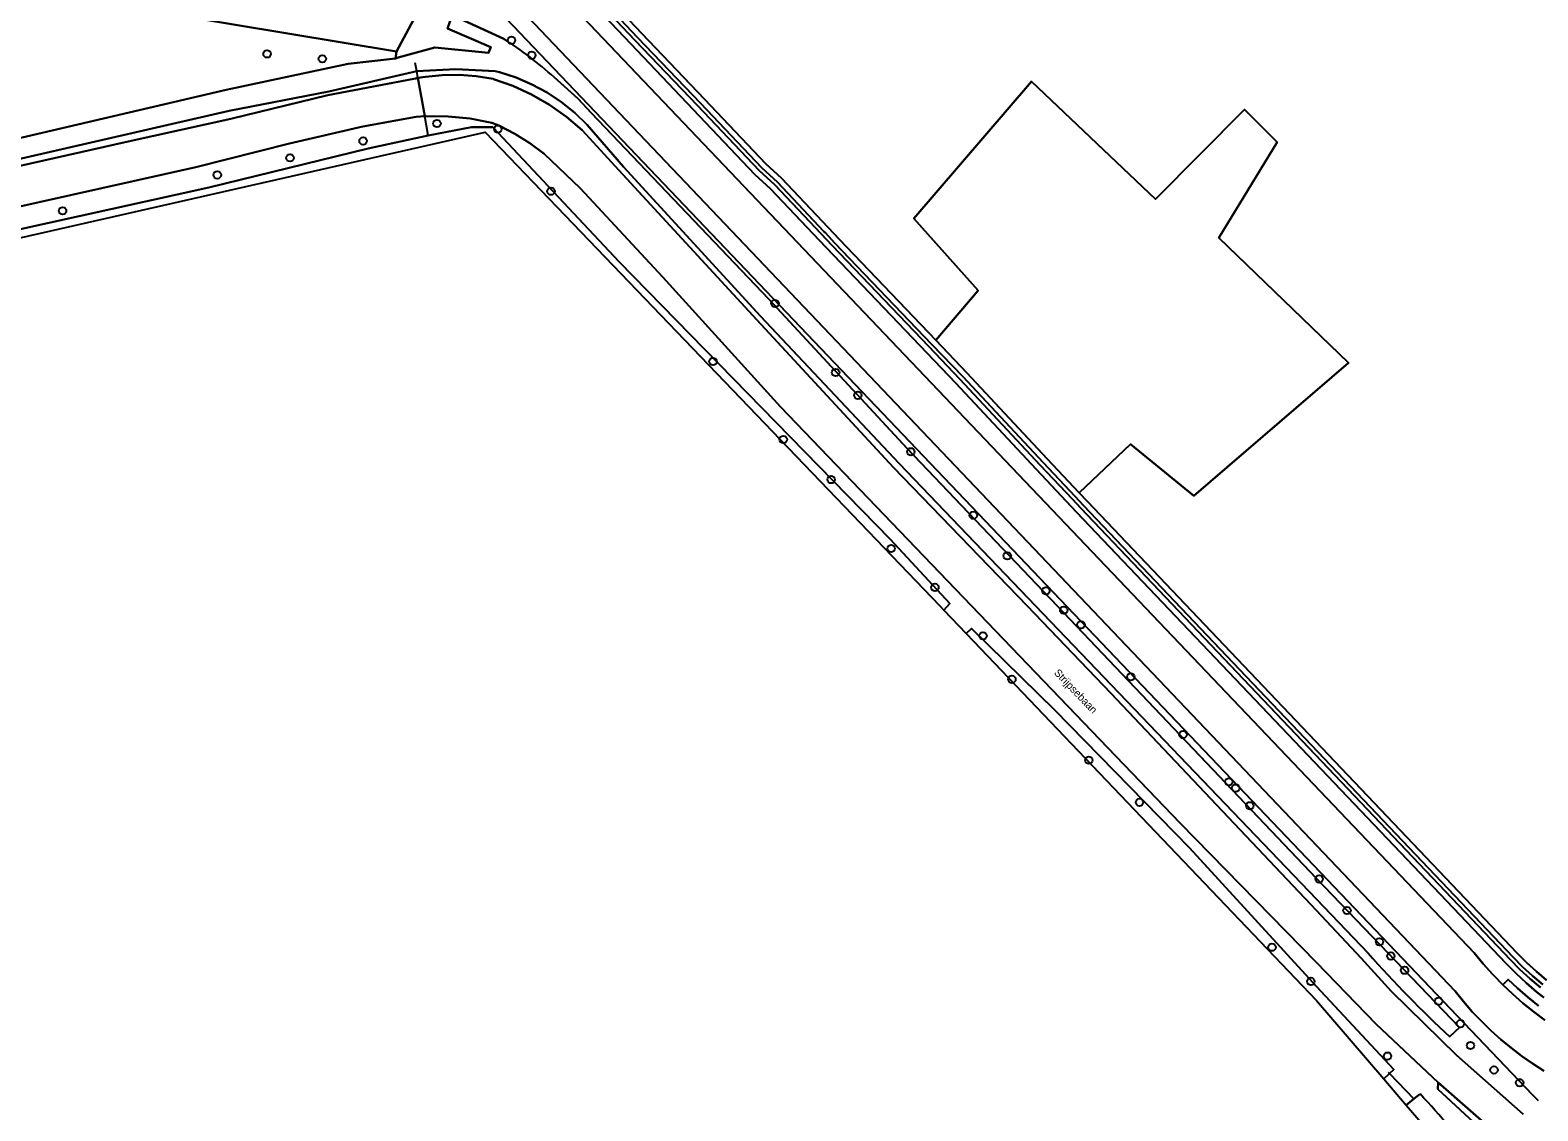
# Model space of a CAD drawing. Extents: x 152881 to 155736, y 382924 to 386919.
# Drawn here: x 153831.1 to 154029.1, y 383183.7 to 383325.6 of the extents above; entities that cross this region are included whole.
import ezdxf

# ---------------------------------------------------------------- set-up
doc = ezdxf.new("R2010")
doc.units = 0
for name, color, linetype in [('IMGEO_Boom', 7, 'Continuous'), ('IMGEO_Duiker', 7, 'Continuous'), ('IMGEO_Gemengd_bos', 7, 'Continuous'), ('IMGEO_Groenvoorziening', 7, 'Continuous'), ('IMGEO_Hek', 7, 'Continuous'), ('IMGEO_Loofbos', 7, 'Continuous'), ('IMGEO_Oever', 7, 'Continuous'), ('IMGEO_Openbare_ruimte_label', 7, 'Continuous'), ('IMGEO_Rijbaan_lokaal_gesloten', 7, 'Continuous'), ('IMGEO_Rijbaan_lokaal_halfverhard', 7, 'Continuous'), ('IMGEO_Sloot', 7, 'Continuous'), ('IMGEO_Terreindeel_halfverhard', 7, 'Continuous'), ('IMGEO_Waterloop', 7, 'Continuous')]:
    doc.layers.add(name, color=color, linetype=linetype)

msp = doc.modelspace()

# ---------------------------------------------------------------- linework, layer by layer
at = {"layer": 'IMGEO_Boom'}
for centre in [(153894.33, 383324.27), (153862.24, 383322.48), (153869.49, 383321.83), (153896.99, 383322.3), (153884.54, 383313.35), (153892.54, 383312.61), (153874.84, 383311.05), (153865.25, 383308.83), (153855.7, 383306.59), (153899.51, 383304.45), (153835.39, 383301.88), (153928.93, 383289.72), (153920.79, 383282.1), (153936.88, 383280.65), (153939.8, 383277.66), (153930.01, 383271.86), (153946.76, 383270.25), (153936.3, 383266.59), (153954.96, 383261.91), (153944.17, 383257.55), (153959.42, 383256.58), (153949.92, 383252.44), (153964.49, 383251.99), (153966.83, 383249.45), (153969.1, 383247.53), (153956.23, 383246.08), (153975.64, 383240.7), (153960.03, 383240.37), (153982.49, 383233.11), (153970.13, 383229.75), (153988.5, 383226.9), (153989.41, 383226.09), (153976.77, 383224.22), (153991.26, 383223.77), (154000.36, 383214.15), (154004.02, 383210.02), (153994.17, 383205.19), (154008.28, 383205.9), (154009.77, 383204.04), (154011.58, 383202.17), (153999.28, 383200.71), (154016.05, 383198.11), (154018.91, 383195.16), (154020.24, 383192.29), (154009.33, 383190.9), (154023.32, 383189.07), (154026.69, 383187.4)]:
    msp.add_circle(centre, 0.489, dxfattribs=at)
at = {"layer": 'IMGEO_Duiker'}
for points in [[(153883.39, 383311.77), (153882.94, 383314.3), (153882.05, 383319.32), (153881.89, 383320.23), (153881.7, 383321.3)], [(154009.42, 383188.81), (154009.62, 383188.6), (154012.79, 383185.27)]]:
    msp.add_lwpolyline(points, dxfattribs=at)
at = {"layer": 'IMGEO_Gemengd_bos'}
for points in [[(153856.86, 383317.78), (153872.87, 383321.17), (153879.1, 383321.89), (153879.1, 383321.89), (153879.25, 383322.78), (153729.12, 383347.72), (153692.52, 383353.78), (153631.89, 383257.44), (153642.33, 383259.86)], [(153671.21, 383274.68), (153677.03, 383276.15), (153686.2, 383277.61), (153694.24, 383279.54), (153731.18, 383288.41), (153856.86, 383317.78)]]:
    msp.add_lwpolyline(points, dxfattribs=at)
at = {"layer": 'IMGEO_Groenvoorziening'}
for points in [[(153631.89, 383257.44), (153692.52, 383353.78), (153729.12, 383347.72), (153879.25, 383322.78), (153882.71, 383329.32), (153859.34, 383451.1), (154096.71, 383496.04), (154210.76, 383548.09)], [(154096.71, 383496.04), (153859.34, 383451.1), (153882.71, 383329.32), (153882.74, 383329.15), (153891.83, 383329), (154028.39, 383185.82), (154029.12, 383185.06)], [(153898.42, 383332.86), (154020.71, 383204.44), (154021.89, 383203.02), (154023.11, 383201.66), (154023.43, 383201.34), (154024.39, 383200.34), (154024.49, 383200.24), (154025.18, 383200.97), (154026.4, 383199.82), (154027.75, 383198.63), (154029.15, 383197.5)], [(154029.85, 383198.59), (154028.94, 383199.31), (154027.55, 383200.5), (154026.21, 383201.75), (154024.92, 383203.04), (153968.51, 383262.33), (153963.21, 383267.96), (153952.67, 383279.23), (153934.71, 383298.03), (153928.33, 383304.77), (153926.29, 383306.65), (153918.2, 383315.18), (153909.98, 383323.79), (153900.28, 383334.06)], [(154029.86, 383188.98), (154028.39, 383189.91), (154026.96, 383190.91), (154025.56, 383191.97), (154024.22, 383193.08), (154022.92, 383194.25), (154021.67, 383195.47), (154020.46, 383196.73), (154019.32, 383198.05), (154018.23, 383199.42), (153892.95, 383331.06)], [(154029.12, 383185.06), (154028.39, 383185.82), (153891.83, 383329), (153882.74, 383329.15), (153882.71, 383329.32), (153879.25, 383322.78), (153879.1, 383321.89), (153879.46, 383321.99), (153884.26, 383323.32), (153891.31, 383322.64), (153891.6, 383323.36), (153885.94, 383325.81), (153886.55, 383327.57), (153893.3, 383324.48)], [(153963.14, 383250), (153945.22, 383268.71), (153927.04, 383288.03), (153909.03, 383307.64), (153904.28, 383313.18), (153902.65, 383314.74), (153900.88, 383316.16), (153898.99, 383317.4), (153897, 383318.48), (153894.92, 383319.37), (153892.77, 383320.07), (153892.17, 383320.23), (153887.01, 383320.46), (153881.89, 383320.23), (153870.36, 383317.54), (153857.26, 383315.01), (153694.93, 383277.76), (153694.24, 383279.54), (153686.2, 383277.61), (153686.5, 383276.05), (153672.56, 383272.44)], [(153781.6, 383296.94), (153844.02, 383310.97), (153857.47, 383313.95), (153870.23, 383317.05), (153881.49, 383319.21), (153881.77, 383319.27), (153882.05, 383319.32), (153883.02, 383319.48), (153885.24, 383319.71), (153887.48, 383319.74), (153889.7, 383319.57), (153891.91, 383319.19), (153891.95, 383319.18), (153894.5, 383318.27), (153896.96, 383317.14), (153899.32, 383315.79), (153901.54, 383314.23), (153903.61, 383312.49), (153908.43, 383307.22), (153926.54, 383287.57), (153944.5, 383268.19), (153962.01, 383250), (153973.03, 383238.56), (154000, 383210), (154005.89, 383203.77), (154009.85, 383199.39), (154018.39, 383191.01), (154027.14, 383183.27)], [(153899.93, 383319.42), (153903.02, 383316.61), (153904.84, 383314.7), (153928.13, 383290.29), (153946.29, 383270.68), (153965.97, 383250), (154000, 383214.23), (154018.8, 383194.64), (154017.52, 383193.45)], [(154023.57, 383179.52), (154015.93, 383186.56), (154015.99, 383187.44), (154007.84, 383195.08), (154000, 383203.18), (153982.11, 383221.49), (153954.73, 383250), (153929.63, 383276.14), (153914.2, 383293.17), (153903.34, 383304.86), (153898.63, 383309.35), (153896.75, 383310.76), (153894.75, 383312.01), (153892.65, 383313.07), (153891.75, 383313.45), (153888.9, 383313.99), (153886.02, 383314.28), (153883.13, 383314.3), (153882.94, 383314.3), (153881.79, 383314.23), (153874.8, 383312.97), (153865.19, 383310.72), (153852.87, 383307.59), (153733.15, 383280.88)], [(153735.39, 383278.59), (153854.57, 383304.93), (153875.51, 383310.08), (153883.39, 383311.77), (153889.07, 383312.85), (153891.86, 383312.86), (153908.47, 383295.19), (153944.04, 383258.78), (153951.89, 383250.32), (153951.1, 383249.43), (153951.1, 383249.43), (153954.01, 383246.38), (153954.72, 383247.04), (153965.68, 383236.31), (153983.35, 383218.24), (154000, 383200.02), (154010.17, 383189.12), (154009.62, 383188.6), (154008.85, 383187.9), (154011.8, 383184.47), (154011.81, 383184.46), (154012.79, 383185.27), (154013.6, 383185.92)], [(154006.79, 383204.41), (154000, 383211.51), (153963.14, 383250)]]:
    msp.add_lwpolyline(points, dxfattribs=at)
msp.add_lwpolyline([(153968.87, 383264.87), (153975.58, 383271.26), (153983.93, 383264.48), (154004.2, 383281.92), (153987.18, 383298.34), (153994.85, 383310.89), (153990.56, 383315.18), (153978.89, 383303.41), (153962.6, 383318.87), (153947.13, 383300.88), (153955.61, 383291.44), (153950.02, 383284.91), (153954.12, 383280.62), (153964.66, 383269.33)], close=True, dxfattribs=at)
for centre, radius, start, end in [((153865.83, 383281.67), 50.86, 47.9083, 57.3131), ((154120.84, 383305.3), 152.27, 221.4967, 227.2729), ((153949.96, 383124.85), 88.21, 36.2056, 43.8165)]:
    msp.add_arc(centre, radius, start, end, dxfattribs=at)
at = {"layer": 'IMGEO_Hek'}
for points in [[(153469.72, 383000.07), (153586.51, 383185.61), (153598.23, 383208.99), (153609.84, 383223.7), (153623.81, 383244.6), (153692.52, 383353.78), (153729.12, 383347.72), (153879.25, 383322.78), (153882.71, 383329.32)], [(153882.74, 383329.15), (153891.83, 383329), (154028.39, 383185.82)], [(154028.39, 383185.82), (154029.12, 383185.06)]]:
    msp.add_lwpolyline(points, dxfattribs=at)
at = {"layer": 'IMGEO_Loofbos'}
msp.add_lwpolyline([(153901.73, 383335.43), (153911.44, 383325.16), (153919.66, 383316.55), (153927.74, 383308.03), (153929.79, 383306.15), (153935.89, 383299.69), (153937.34, 383298.17), (153950.02, 383284.91), (153955.61, 383291.44), (153947.13, 383300.88), (153962.6, 383318.87), (153978.89, 383303.41), (153990.56, 383315.18), (153994.85, 383310.89), (153987.18, 383298.34), (154004.2, 383281.92), (153983.93, 383264.48), (153975.58, 383271.26), (153968.87, 383264.87), (153969.96, 383263.71), (154026.37, 383204.42), (154027.6, 383203.18), (154028.88, 383201.99), (154030.21, 383200.86)], dxfattribs=at)
at = {"layer": 'IMGEO_Oever'}
for points in [[(154029.41, 383199.89), (154028.05, 383201.06), (154026.73, 383202.29), (154025.47, 383203.55), (153969.06, 383262.85), (153967.96, 383264.01), (153963.75, 383268.47), (153953.21, 383279.76), (153949.11, 383284.05), (153936.43, 383297.31), (153934.99, 383298.84), (153928.89, 383305.29), (153926.84, 383307.16), (153918.76, 383315.69), (153910.53, 383324.3), (153900.82, 383334.58)], [(153901.18, 383334.92), (153910.89, 383324.65), (153919.12, 383316.03), (153927.19, 383307.52), (153929.24, 383305.64), (153935.35, 383299.18), (153935.54, 383298.98), (153935.94, 383298.55), (153936.8, 383297.65), (153949.47, 383284.39), (153953.57, 383280.11), (153964.11, 383268.82), (153968.33, 383264.35), (153969.42, 383263.19), (154025.83, 383203.9), (154027.08, 383202.64), (154028.38, 383201.43), (154029.73, 383200.28)], [(154030.21, 383200.86), (154028.88, 383201.99), (154027.6, 383203.18), (154026.37, 383204.42), (153969.96, 383263.71), (153968.87, 383264.87), (153964.66, 383269.33), (153954.12, 383280.62), (153950.02, 383284.91), (153937.34, 383298.17), (153935.89, 383299.69), (153929.79, 383306.15), (153927.74, 383308.03), (153919.66, 383316.55), (153911.44, 383325.16), (153901.73, 383335.43)], [(153900.28, 383334.06), (153909.98, 383323.79), (153918.2, 383315.18), (153926.29, 383306.65), (153928.33, 383304.77), (153934.71, 383298.03), (153952.67, 383279.23), (153963.21, 383267.96), (153968.51, 383262.33), (154024.92, 383203.04), (154026.21, 383201.75), (154027.55, 383200.5), (154028.94, 383199.31), (154029.85, 383198.59)]]:
    msp.add_lwpolyline(points, dxfattribs=at)
at = {"layer": 'IMGEO_Rijbaan_lokaal_gesloten'}
for points in [[(154030.01, 383195.62), (154028.54, 383196.71), (154027.11, 383197.87), (154025.73, 383199.08), (154024.49, 383200.24), (154024.39, 383200.34), (154023.43, 383201.34), (154023.11, 383201.66), (154021.89, 383203.02), (154020.71, 383204.44), (153898.42, 383332.86)], [(153892.95, 383331.06), (154018.23, 383199.42), (154019.32, 383198.05), (154020.46, 383196.73), (154021.67, 383195.47), (154022.92, 383194.25), (154024.22, 383193.08), (154025.56, 383191.97), (154026.96, 383190.91), (154028.39, 383189.91), (154029.86, 383188.98)]]:
    msp.add_lwpolyline(points, dxfattribs=at)
at = {"layer": 'IMGEO_Rijbaan_lokaal_halfverhard'}
for points in [[(153678.39, 383268.03), (153707.05, 383275.08), (153733.15, 383280.88), (153852.87, 383307.59), (153865.19, 383310.72), (153874.8, 383312.97), (153881.79, 383314.23), (153882.94, 383314.3), (153882.05, 383319.32), (153881.77, 383319.27), (153881.49, 383319.21), (153870.23, 383317.05), (153857.47, 383313.95), (153844.02, 383310.97), (153781.6, 383296.94), (153754.73, 383291.13), (153729.71, 383285.1), (153677.51, 383272.68), (153671.82, 383271.14)], [(154027.14, 383183.27), (154018.39, 383191.01), (154009.85, 383199.39), (154005.89, 383203.77), (154000, 383210), (153973.03, 383238.56), (153962.01, 383250), (153944.5, 383268.19), (153926.54, 383287.57), (153908.43, 383307.22), (153903.61, 383312.49), (153901.54, 383314.23), (153899.32, 383315.79), (153896.96, 383317.14), (153894.5, 383318.27), (153891.95, 383319.18), (153891.91, 383319.19), (153889.7, 383319.57), (153887.48, 383319.74), (153885.24, 383319.71), (153883.02, 383319.48), (153882.05, 383319.32), (153882.94, 383314.3), (153883.13, 383314.3), (153886.02, 383314.28), (153888.9, 383313.99), (153891.75, 383313.45), (153892.65, 383313.07), (153894.75, 383312.01), (153896.75, 383310.76), (153898.63, 383309.35), (153903.34, 383304.86), (153914.2, 383293.17), (153929.63, 383276.14), (153954.73, 383250), (153982.11, 383221.49), (154000, 383203.18), (154007.84, 383195.08), (154015.99, 383187.44), (154024.47, 383179.99)]]:
    msp.add_lwpolyline(points, dxfattribs=at)
msp.add_lwpolyline([(154036.35, 383164.54), (154036.61, 383165.57), (154037.13, 383166.34), (154037.85, 383167.04), (154038.82, 383167.72), (154039.68, 383167.95), (154041.81, 383167.83), (154045.84, 383166.42), (154049.17, 383165.75), (154045.2, 383167.4), (154035.94, 383172.13), (154030.85, 383175.27), (154024.47, 383179.99), (154015.99, 383187.44), (154015.93, 383186.56), (154023.57, 383179.52), (154025.99, 383176.29), (154030.54, 383169.34), (154031.68, 383166.72), (154032.13, 383165.8), (154036.3, 383164.55)], close=True, dxfattribs=at)
at = {"layer": 'IMGEO_Sloot'}
for points in [[(154013.6, 383185.92), (154012.79, 383185.27), (154011.81, 383184.46)], [(154011.81, 383184.46), (154019.3, 383175.75), (154026.39, 383167.51), (154027.78, 383167.09), (154029.04, 383166.72), (154027.96, 383168.24), (154026.65, 383170.02), (154025.32, 383171.79), (154024.9, 383172.32), (154024.12, 383173.31), (154023.95, 383173.53), (154022.55, 383175.25), (154021.13, 383176.95)]]:
    msp.add_lwpolyline(points, dxfattribs=at)
msp.add_arc((153949.96, 383124.85), 88.21, 36.2056, 43.8165, dxfattribs=at)
at = {"layer": 'IMGEO_Terreindeel_halfverhard'}
msp.add_lwpolyline([(154029.15, 383197.5), (154027.75, 383198.63), (154026.4, 383199.82), (154025.18, 383200.97), (154024.49, 383200.24), (154025.73, 383199.08), (154027.11, 383197.87), (154028.54, 383196.71), (154030.01, 383195.62)], dxfattribs=at)
at = {"layer": 'IMGEO_Waterloop'}
for points in [[(153900.82, 383334.58), (153910.53, 383324.3), (153918.76, 383315.69), (153926.84, 383307.16), (153928.89, 383305.29), (153934.99, 383298.84), (153936.43, 383297.31), (153949.11, 383284.05), (153953.21, 383279.76), (153963.75, 383268.47), (153967.96, 383264.01), (153969.06, 383262.85), (154025.47, 383203.55), (154026.73, 383202.29), (154028.05, 383201.06), (154029.41, 383199.89)], [(154029.73, 383200.28), (154028.38, 383201.43), (154027.08, 383202.64), (154025.83, 383203.9), (153969.42, 383263.19), (153968.33, 383264.35), (153964.11, 383268.82), (153953.57, 383280.11), (153949.47, 383284.39), (153936.8, 383297.65), (153935.94, 383298.55), (153935.54, 383298.98), (153935.35, 383299.18), (153929.24, 383305.64), (153927.19, 383307.52), (153919.12, 383316.03), (153910.89, 383324.65), (153901.18, 383334.92)], [(153893.3, 383324.48), (153886.55, 383327.57), (153885.94, 383325.81), (153891.6, 383323.36), (153891.31, 383322.64), (153884.26, 383323.32), (153879.46, 383321.99), (153879.1, 383321.89), (153879.1, 383321.89), (153872.87, 383321.17), (153856.86, 383317.78), (153731.18, 383288.41)], [(153694.93, 383277.76), (153857.26, 383315.01), (153870.36, 383317.54), (153881.89, 383320.23), (153887.01, 383320.46), (153892.17, 383320.23), (153892.77, 383320.07), (153894.92, 383319.37), (153897, 383318.48), (153898.99, 383317.4), (153900.88, 383316.16), (153902.65, 383314.74), (153904.28, 383313.18), (153909.03, 383307.64), (153927.04, 383288.03), (153945.22, 383268.71), (153963.14, 383250), (154000, 383211.51), (154006.79, 383204.41)], [(153928.13, 383290.29), (153904.84, 383314.7), (153903.02, 383316.61), (153899.93, 383319.42)], [(153651.06, 383251.81), (153652.41, 383252.78), (153658.19, 383256.89), (153663.25, 383260.49), (153663.77, 383260.61), (153669.85, 383261.99), (153890.87, 383312.22), (153950.55, 383250), (153951.1, 383249.43), (153951.89, 383250.32), (153944.04, 383258.78), (153908.47, 383295.19), (153891.86, 383312.86), (153889.07, 383312.85), (153883.39, 383311.77), (153875.51, 383310.08), (153854.57, 383304.93), (153735.39, 383278.59), (153710.59, 383272.44), (153679.58, 383265.48)], [(154017.52, 383193.45), (154018.8, 383194.64), (154000, 383214.23), (153965.97, 383250), (153946.29, 383270.68), (153928.13, 383290.29)]]:
    msp.add_lwpolyline(points, dxfattribs=at)
msp.add_lwpolyline([(154008.85, 383187.9), (154009.62, 383188.6), (154010.17, 383189.12), (154000, 383200.02), (153983.35, 383218.24), (153965.68, 383236.31), (153954.72, 383247.04), (153954.01, 383246.38), (153954.01, 383246.38), (154000, 383198.19), (154008.85, 383187.9)], close=True, dxfattribs=at)
for centre, radius, start, end in [((153865.83, 383281.67), 50.86, 47.9083, 57.3131), ((154120.84, 383305.3), 152.27, 221.4967, 227.2729)]:
    msp.add_arc(centre, radius, start, end, dxfattribs=at)

# ---------------------------------------------------------------- texts
at = {"layer": 'IMGEO_Openbare_ruimte_label'}
msp.add_text('Strijpsebaan', height=1, rotation=313.8656, dxfattribs=at).set_placement((153965.48, 383241.15))

doc.saveas('drawing.dxf')
